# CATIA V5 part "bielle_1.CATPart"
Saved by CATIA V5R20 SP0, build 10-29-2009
Part number: sqlt_bielle_1
Publications: "longueur_bielle_1", "rayon_pivot_bati", "rayon_pivot_bielle", "épaisseur_piece", "Plan.1", "Point.1", "Droite.1", "Point.2", "Point.4", "Point.5", "Point.6", "Droite.2", "Droite.3", "Plan.2", "Plan.3", "Point.7", "Point.8"
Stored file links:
  D:\ecole\thinkmotion\IAO\bielle_1.CATPart
  D:\ecole\thinkmotion\IAO\sqlt mecanisme coulisseau.CATProduct
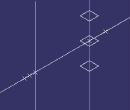
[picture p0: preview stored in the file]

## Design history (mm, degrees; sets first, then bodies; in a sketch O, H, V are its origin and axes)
Parameters
  longueur_bielle_1 = 50 mm {= External.longueur_bielle_1}
  rayon_pivot_bati = 10 mm {= External.rayon_pivot_bati}
  rayon_pivot_bielle = 5 mm {= External.rayon_pivot_bielle}
  `épaisseur_piece` = 20 mm {= `External.épaisseur_piece`}
External parameters (linked from other documents)
  External.longueur_bielle_1 = 50 mm
  External.rayon_pivot_bati = 10 mm
  External.rayon_pivot_bielle = 5 mm
  `External.épaisseur_piece` = 20 mm
Set1 "sqlt_bielle_2"
  Plane1: type Offset, RefPlane xy-plane, Offset 0
  Point1: (0, 0, 0)
  Line1: type PtDir, RefPoint Point1, Direction yz-plane, Start 0, End 20
  Point2: type OnCurve, Support Line1, Length 50 {= longueur_bielle_1}
  Point3: (-15 {= -rayon_pivot_bati -5mm}, 0, 0)
  Point4: (5 {= rayon_pivot_bielle}, 0, 0), relative to Point2
  Line2: type PtDir, RefPoint Point1, Direction Plane1, Start 0, End 20
  Line3: type PtDir, RefPoint Point2, Direction Plane1, Start 0, End 20
  Plane2: type Offset, RefPlane xy-plane, Offset 20 {= `épaisseur_piece`}
  Plane3: type Offset, RefPlane xy-plane, Offset 20 {= `épaisseur_piece`}, reversed
  Point5: (10 {= rayon_pivot_bielle +5mm}, 0, 0), relative to Point2
Body1 (main body)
